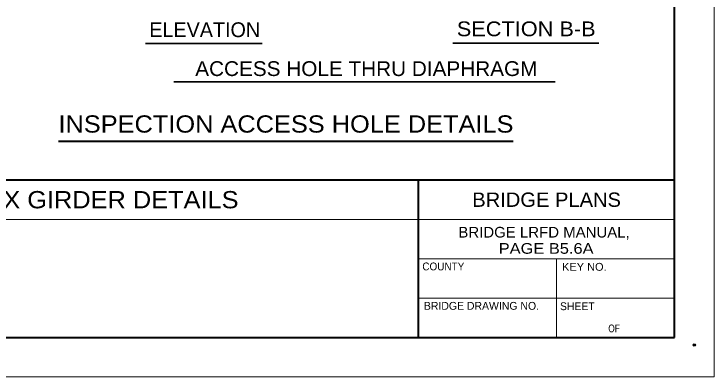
# Model space of a CAD drawing. Extents: x 0 to 34, y 0 to 23.4.
# Drawn here: x 25.11 to 34, y 0 to 4.61 of the extents above; entities that cross this region are included whole.
import ezdxf
from ezdxf.enums import TextEntityAlignment as Align

# ---------------------------------------------------------------- set-up
doc = ezdxf.new("R2010")
doc.units = 0
doc.header["$LTSCALE"] = 0.062
doc.header["$PDMODE"] = 32
doc.header["$PDSIZE"] = 0.031
doc.layers.add('1', color=7, linetype='Continuous', lineweight=40)
doc.layers.add('4', color=7, linetype='Continuous', lineweight=13)
doc.layers.add('49', color=7, linetype='Continuous')

msp = doc.modelspace()

# ---------------------------------------------------------------- linework, layer by layer
at = {"layer": '1'}
for p, q in [((19.25, 2.5), (33.5, 2.5)), ((30.25, 0.5), (30.25, 2.5))]:
    msp.add_line(p, q, dxfattribs=at)
at = {"layer": '1', "lineweight": 13}
for p, q in [((22.25, 2), (33.5, 2)), ((30.25, 1.5), (33.5, 1.5)), ((32, 0.5), (32, 1.5)), ((30.25, 1), (33.5, 1))]:
    msp.add_line(p, q, dxfattribs=at)
for points in [[(34, 0), (34, 22), (0, 22)], [(0, 22), (0, 0), (34, 0)]]:
    msp.add_lwpolyline(points, dxfattribs=at)
at = {"layer": '1'}
msp.add_lwpolyline([(33.5, 0.5), (33.5, 21.5), (1.5, 21.5), (1.5, 0.5)], close=True, dxfattribs=at)
at = {"layer": '4', "lineweight": 35}
for p, q in [((26.7824, 4.23318), (28.26547, 4.23318)), ((30.68391, 4.23536), (32.53682, 4.23536)), ((27.14083, 3.74708), (31.9851, 3.74708))]:
    msp.add_line(p, q, dxfattribs=at)
at = {"layer": '4', "lineweight": 40}
msp.add_line((25.6763, 2.99109), (31.45109, 2.99109), dxfattribs=at)
at = {"layer": '49'}
msp.add_point((33.75, 0.40625), dxfattribs=at)

# ---------------------------------------------------------------- texts
at = {"layer": '4'}
for s, height, p in [('ELEVATION', 0.1875, (27.53422, 4.31302)), ('BRIDGE DRAWING NO.', 0.09938, (31.0476, 0.85313)), ('SHEET', 0.09875, (32.26503, 0.84813))]:
    msp.add_text(s, height=height, dxfattribs=at).set_placement(p, align=Align.CENTER)
for s, height, width, p in [('SECTION B-B', 0.1875, 1.1, (31.6157, 4.32422)), ('ACCESS HOLE THRU DIAPHRAGM', 0.1875, 1.05, (29.58612, 3.81927)), ('INSPECTION ACCESS HOLE DETAILS', 0.2188, 1.1, (28.56581, 3.10109)), ('BOX GIRDER DETAILS', 0.2188, 1.1, (26.23792, 2.14062)), ('BRIDGE PLANS', 0.1819, 1.05, (31.87497, 2.15906)), ('BRIDGE LRFD MANUAL, ', 0.1354, 1.05, (31.8688, 1.76943)), ('PAGE B5.6A', 0.1354, 1.15, (31.8688, 1.5637)), ('COUNTY', 0.09938, 0.95, (30.56372, 1.35313)), ('KEY NO.', 0.09938, 1.05, (32.35375, 1.34813)), ('OF', 0.09875, 0.8, (32.73122, 0.56688))]:
    msp.add_text(s, height=height, dxfattribs=dict(at, width=width)).set_placement(p, align=Align.CENTER)

doc.saveas('drawing.dxf')
